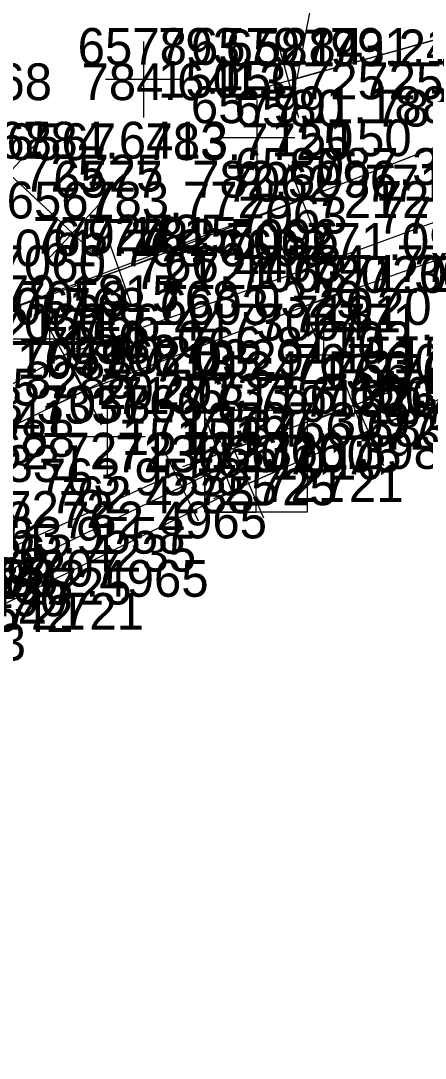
# Model space of a CAD drawing. Extents: x 1602514 to 1609837, y 863887 to 871157.
# Drawn here: x 1604583.5 to 1604666.7, y 865888.8 to 866102.1 of the extents above; entities that cross this region are included whole.
import ezdxf

# ---------------------------------------------------------------- set-up
doc = ezdxf.new("R2010")
doc.units = 0
for name, color, linetype in [('Default', 7, 'Continuous'), ('Survey-Point', 7, 'Continuous'), ('Survey-Spot bituminous', 7, 'Continuous'), ('Survey-Spot dirt', 7, 'Continuous'), ('Survey-Text-Elevation', 7, 'Continuous'), ('Survey-Text-Feature', 7, 'Continuous'), ('Survey-Text-Name and Number', 7, 'Continuous'), ('Survey-Utility-poles', 7, 'Continuous'), ('Survey-Vegetation trees', 7, 'Continuous')]:
    doc.layers.add(name, color=color, linetype=linetype)

msp = doc.modelspace()

# ---------------------------------------------------------------- linework, layer by layer
at = {"layer": 'Default'}
for points in [[(1604317.66, 865825.88), (1604343.15, 865856.06), (1604377.77, 865885.95), (1604413.36, 865926.28), (1604468.55, 865975.61), (1604530.26, 866007.99), (1604571, 866039.19), (1604603.77, 866050.72), (1604641.34, 866065.32), (1604709.14, 866091.96), (1604755.83, 866103.01), (1604799.76, 866108.85), (1604851.09, 866123.18), (1604880.6, 866134.38), (1604938.3, 866169.31)], [(1604317.66, 865825.88), (1604343.15, 865856.06), (1604377.77, 865885.95), (1604413.36, 865926.28), (1604468.55, 865975.61), (1604530.26, 866007.99), (1604571, 866039.19), (1604603.77, 866050.72), (1604641.34, 866065.32), (1604709.14, 866091.96), (1604755.83, 866103.01), (1604799.76, 866108.85), (1604851.09, 866123.18), (1604880.6, 866134.38), (1604938.3, 866169.31)], [(1604418.07, 865911.75), (1604456.72, 865946.46), (1604484.55, 865966.8), (1604519.27, 865986.42), (1604552.11, 866004.25), (1604596.62, 866026.02), (1604641.77, 866043.32), (1604684.55, 866058.32), (1604714.78, 866069.08), (1604743.56, 866078.38), (1604785.26, 866088.44), (1604832.44, 866095.89), (1604871.37, 866104.92), (1604903.81, 866116.87), (1604930.07, 866130.29), (1604954.76, 866146.48)], [(1604418.07, 865911.75), (1604456.72, 865946.46), (1604484.55, 865966.8), (1604519.27, 865986.42), (1604552.11, 866004.25), (1604596.62, 866026.02), (1604641.77, 866043.32), (1604684.55, 866058.32), (1604714.78, 866069.08), (1604743.56, 866078.38), (1604785.26, 866088.44), (1604832.44, 866095.89), (1604871.37, 866104.92), (1604903.81, 866116.87), (1604930.07, 866130.29), (1604954.76, 866146.48)], [(1604969.01, 866130.08), (1604947.53, 866114.66), (1604915.9, 866098.08), (1604878.31, 866083.75), (1604838.9, 866074.21), (1604795.51, 866067.39), (1604763.14, 866059.96), (1604741.7, 866054.99), (1604695.88, 866039.38), (1604651.97, 866023), (1604624.19, 866013.05), (1604572.23, 865989.52), (1604533.06, 865968.94), (1604507.4, 865954.89), (1604477.08, 865934.29), (1604465.98, 865925.57), (1604435.67, 865897.76)], [(1604969.01, 866130.08), (1604947.53, 866114.66), (1604915.9, 866098.08), (1604878.31, 866083.75), (1604838.9, 866074.21), (1604795.51, 866067.39), (1604763.14, 866059.96), (1604741.7, 866054.99), (1604695.88, 866039.38), (1604651.97, 866023), (1604624.19, 866013.05), (1604572.23, 865989.52), (1604533.06, 865968.94), (1604507.4, 865954.89), (1604477.08, 865934.29), (1604465.98, 865925.57), (1604435.67, 865897.76)], [(1604947.43, 866111.35), (1604916.99, 866095.23), (1604887.83, 866078.59), (1604869.51, 866073.57), (1604839.7, 866068.1), (1604796.01, 866064.89), (1604764.05, 866057.49), (1604744.43, 866051.86), (1604696.67, 866036.33), (1604655.01, 866017.68), (1604630.39, 866006.95), (1604577.01, 865980.66), (1604537.2, 865961.45), (1604527.45, 865955.57)], [(1604947.43, 866111.35), (1604916.99, 866095.23), (1604887.83, 866078.59), (1604869.51, 866073.57), (1604839.7, 866068.1), (1604796.01, 866064.89), (1604764.05, 866057.49), (1604744.43, 866051.86), (1604696.67, 866036.33), (1604655.01, 866017.68), (1604630.39, 866006.95), (1604577.01, 865980.66), (1604537.2, 865961.45), (1604527.45, 865955.57)], [(1604638.56, 866089.7), (1604688.07, 866103.57), (1604751.24, 866108.42)], [(1604638.56, 866089.7), (1604688.07, 866103.57), (1604751.24, 866108.42)], [(1604594.18, 866058.42), (1604581.01, 866070.74), (1604536, 866101.64)], [(1604594.18, 866058.42), (1604581.01, 866070.74), (1604536, 866101.64)], [(1604322.98, 865821.98), (1604323.18, 865824.62), (1604347.39, 865848.47), (1604386.06, 865884.59), (1604416.66, 865913.17), (1604455.42, 865948.07), (1604483.63, 865969.92), (1604515.11, 865988.99), (1604549.54, 866009.43), (1604592.4, 866033.32), (1604639.22, 866049.9), (1604682.4, 866065.75), (1604710.78, 866076.01), (1604734.96, 866082.18)], [(1604322.98, 865821.98), (1604323.18, 865824.62), (1604347.39, 865848.47), (1604386.06, 865884.59), (1604416.66, 865913.17), (1604455.42, 865948.07), (1604483.63, 865969.92), (1604515.11, 865988.99), (1604549.54, 866009.43), (1604592.4, 866033.32), (1604639.22, 866049.9), (1604682.4, 866065.75), (1604710.78, 866076.01), (1604734.96, 866082.18)], [(1604616.65, 866006.26), (1604574.45, 865985.84), (1604535.94, 865964.64), (1604524.8, 865957.18), (1604517.47, 865951.2), (1604513.27, 865945.54)], [(1604616.65, 866006.26), (1604574.45, 865985.84), (1604535.94, 865964.64), (1604524.8, 865957.18), (1604517.47, 865951.2), (1604513.27, 865945.54)]]:
    msp.add_lwpolyline(points, dxfattribs=at)
at = {"layer": 'Survey-Point'}
for p, q in [((1604636.45, 866097.23), (1604640.67, 866082.18)), ((1604646.08, 866091.81), (1604631.04, 866087.6)), ((1604575.31, 866076.08), (1604586.72, 866065.4)), ((1604575.68, 866065.04), (1604586.35, 866076.44)), ((1604638.51, 866072.6), (1604644.17, 866058.04)), ((1604648.62, 866068.15), (1604634.06, 866062.49)), ((1604588.47, 866063.76), (1604599.88, 866053.08)), ((1604588.84, 866052.72), (1604599.51, 866064.13)), ((1604601.17, 866058.09), (1604606.36, 866043.35)), ((1604636.61, 866057.26), (1604641.83, 866042.53)), ((1604611.14, 866053.32), (1604596.4, 866048.13)), ((1604646.59, 866052.51), (1604631.86, 866047.29)), ((1604638.98, 866050.61), (1604644.56, 866036.02)), ((1604649.07, 866046.11), (1604634.47, 866040.52)), ((1604588.59, 866040.14), (1604596.2, 866026.5)), ((1604599.22, 866037.12), (1604585.57, 866029.52)), ((1604593.18, 866033.04), (1604600.05, 866019.01)), ((1604603.64, 866029.46), (1604589.6, 866022.59)), ((1604654.7, 866015.68), (1604649.24, 866030.32)), ((1604644.65, 866020.27), (1604659.29, 866025.73)), ((1604658.21, 866010.55), (1604651.82, 866024.81)), ((1604626.83, 866005.69), (1604621.56, 866020.4)), ((1604647.88, 866014.49), (1604662.14, 866020.87)), ((1604616.84, 866010.41), (1604631.55, 866015.68)), ((1604633.5, 865999.79), (1604627.27, 866014.12)), ((1604620.06, 865999.23), (1604613.25, 866013.29)), ((1604623.22, 866003.83), (1604637.55, 866010.07)), ((1604609.62, 866002.86), (1604623.69, 866009.66)), ((1604570, 865977.2), (1604584.02, 865984.11))]:
    msp.add_line(p, q, dxfattribs=at)
at = {"layer": 'Survey-Spot bituminous'}
for p, q in [((1604645.78, 866041.16), (1604645.78, 866025.54)), ((1604653.59, 866033.35), (1604637.97, 866033.35)), ((1604601.29, 866024.37), (1604601.29, 866008.75)), ((1604609.11, 866016.56), (1604593.48, 866016.56))]:
    msp.add_line(p, q, dxfattribs=at)
at = {"layer": 'Survey-Spot dirt'}
for p, q in [((1604608.77, 866097.81), (1604608.77, 866082.19)), ((1604616.58, 866090), (1604600.96, 866090)), ((1604632.06, 866085.81), (1604632.06, 866070.19)), ((1604639.87, 866078), (1604624.25, 866078)), ((1604589.42, 866044.39), (1604589.42, 866028.77)), ((1604597.23, 866036.58), (1604581.61, 866036.58))]:
    msp.add_line(p, q, dxfattribs=at)
at = {"layer": 'Survey-Utility-poles'}
for points in [[(1604621.42, 866001.03), (1604631.92, 866001.03), (1604631.92, 866022.04), (1604621.42, 866022.04)], [(1604621.42, 866022.04), (1604642.43, 866022.04), (1604642.43, 866001.03), (1604621.42, 866001.03)]]:
    msp.add_lwpolyline(points, close=True, dxfattribs=at)
at = {"layer": 'Survey-Vegetation trees'}
for points in [[(1604936.33, 866180.61), (1604828.34, 866126.3), (1604827.66, 866144.66), (1604799.29, 866162.35), (1604737.82, 866156.32), (1604693.89, 866174.66), (1604669.04, 866176.96), (1604670.6, 866142.06), (1604659.79, 866117.8), (1604667.53, 866114.56), (1604679.44, 866101.15), (1604640.36, 866090.2), (1604645.49, 866116.93), (1604602.11, 866123.38), (1604531.29, 866143.38), (1604483.77, 866157.5), (1604441.77, 866144.36), (1604421.63, 866112.25)], [(1604243.16, 865754.91), (1604317.66, 865825.88), (1604343.54, 865856.39), (1604412.96, 865925.83), (1604470.6, 865976.69), (1604532.4, 866009.63), (1604574.44, 866040.4), (1604646.35, 866067.29), (1604709.79, 866092.12), (1604761.9, 866103.82), (1604800.74, 866109.12), (1604857.49, 866106.02), (1604919.6, 866129.97), (1604961.14, 866155.01)]]:
    msp.add_lwpolyline(points, dxfattribs=at)

# ---------------------------------------------------------------- texts
at = {"layer": 'Survey-Text-Elevation'}
for s, p in [('793.5284', (1604611.77, 866093)), ('793.2423', (1604641.56, 866092.7)), ('791.1881', (1604647.06, 866093)), ('784.6413', (1604596.01, 866085.74)), ('791.1881', (1604635.06, 866081)), ('787.3344', (1604656.34, 866080.32)), ('784.6413', (1604584.01, 866073.74)), ('783.7725', (1604609.18, 866073.42)), ('787.3344', (1604644.34, 866068.32)), ('782.5096', (1604618.77, 866065.72)), ('771.0973', (1604654.22, 866064.9)), ('783.7725', (1604597.18, 866061.42)), ('771.3698', (1604656.77, 866058.32)), ('779.1815', (1604586, 866054.19)), ('782.5096', (1604606.77, 866053.72)), ('768.6603', (1604604.42, 866051.58)), ('771.0973', (1604642.22, 866052.9)), ('766.4473', (1604607.4, 866048.32)), ('771.2481', (1604660.78, 866048.35)), ('771.3698', (1604644.77, 866046.32)), ('779.1815', (1604574, 866042.19)), ('768.0329', (1604611.62, 866041.02)), ('768.6603', (1604592.42, 866039.58)), ('766.4473', (1604595.4, 866036.32)), ('771.2481', (1604648.78, 866036.35)), ('766.8170', (1604616.29, 866031.56)), ('764.1641', (1604563.08, 866028.51)), ('768.0329', (1604599.62, 866029.02)), ('767.3097', (1604639.19, 866028.05)), ('766.6830', (1604646.92, 866026.53)), ('770.0671', (1604654.97, 866026)), ('761.8288', (1604564.54, 866024.43)), ('771.6955', (1604545.26, 866022.99)), ('766.1005', (1604631.65, 866021.26)), ('766.3988', (1604645.39, 866021.95)), ('763.3331', (1604567.11, 866019.25)), ('766.8170', (1604604.29, 866019.56)), ('768.6179', (1604658.01, 866020.68)), ('764.1641', (1604551.08, 866016.51)), ('767.3097', (1604627.19, 866016.05)), ('766.6830', (1604634.92, 866014.53)), ('761.8288', (1604552.54, 866012.43)), ('762.7272', (1604572.46, 866009.83)), ('766.1005', (1604619.65, 866009.26)), ('766.3988', (1604633.39, 866009.95)), ('763.3331', (1604555.11, 866007.25)), ('763.9558', (1604587.23, 866004.52)), ('762.4235', (1604589.45, 866000.84)), ('762.7272', (1604560.46, 865997.83)), ('762.4965', (1604592.01, 865995.66)), ('763.9558', (1604575.23, 865992.52)), ('762.4235', (1604577.45, 865988.84)), ('760.0898', (1604548.06, 865983.94)), ('762.4965', (1604580.01, 865983.66)), ('758.7490', (1604550.94, 865979.64)), ('758.4542', (1604552.2, 865976.45)), ('757.4563', (1604542.45, 865970.57))]:
    msp.add_text(s, height=7.56, dxfattribs=at).set_placement(p)
at = {"layer": 'Survey-Text-Feature'}
for s, p in [('150', (1604611.77, 866086.22)), ('150', (1604623.77, 866086.22)), ('725', (1604641.56, 866085.92)), ('725', (1604653.56, 866085.92)), ('150', (1604635.06, 866074.22)), ('150', (1604647.06, 866074.22)), ('725', (1604584.01, 866066.96)), ('725', (1604596.01, 866066.96)), ('721', (1604644.34, 866061.54)), ('721', (1604656.34, 866061.54)), ('725', (1604597.18, 866054.64)), ('725', (1604609.18, 866054.64)), ('721', (1604606.77, 866046.94)), ('721', (1604618.77, 866046.94)), ('720', (1604642.22, 866046.12)), ('720', (1604654.22, 866046.12)), ('207', (1604644.77, 866039.54)), ('207', (1604656.77, 866039.54)), ('721', (1604574, 866035.41)), ('721', (1604586, 866035.41)), ('150', (1604592.42, 866032.8)), ('150', (1604604.42, 866032.8)), ('720', (1604595.4, 866029.54)), ('720', (1604607.4, 866029.54)), ('151', (1604648.78, 866029.57)), ('151', (1604660.78, 866029.57)), ('207', (1604599.62, 866022.24)), ('207', (1604611.62, 866022.24)), ('207', (1604654.97, 866019.22)), ('721', (1604658.01, 866013.9)), ('151', (1604604.29, 866012.78)), ('151', (1604616.29, 866012.78)), ('207', (1604627.19, 866009.27)), ('207', (1604639.19, 866009.27)), ('10', (1604634.92, 866007.75)), ('10', (1604646.92, 866007.75)), ('725', (1604619.65, 866002.48)), ('725', (1604631.65, 866002.48)), ('721', (1604633.39, 866003.17)), ('721', (1604645.39, 866003.17)), ('151', (1604572.46, 865991.05)), ('207', (1604575.23, 865985.74)), ('207', (1604587.23, 865985.74)), ('725', (1604577.45, 865982.06)), ('725', (1604589.45, 865982.06)), ('721', (1604580.01, 865976.88)), ('721', (1604592.01, 865976.88))]:
    msp.add_text(s, height=7.56, dxfattribs=at).set_placement(p)
at = {"layer": 'Survey-Text-Name and Number'}
for s, p in [('6578', (1604595.23, 866093)), ('6579', (1604618.51, 866093)), ('6581', (1604625.68, 866092.7)), ('6568', (1604567.47, 866085.74)), ('6579', (1604618.51, 866081)), ('6580', (1604627.5, 866080.32)), ('6568', (1604567.47, 866073.74)), ('6567', (1604580.63, 866073.42)), ('6580', (1604627.5, 866068.32)), ('6577', (1604590.22, 866065.72)), ('7062', (1604625.68, 866064.9)), ('6567', (1604580.63, 866061.42)), ('7063', (1604628.23, 866058.32)), ('6577', (1604590.22, 866053.72)), ('7061', (1604576.66, 866051.58)), ('7062', (1604625.68, 866052.9)), ('7060', (1604578.56, 866048.32)), ('7064', (1604632.24, 866048.35)), ('7063', (1604628.23, 866046.32)), ('7059', (1604583.07, 866041.02)), ('7061', (1604576.54, 866039.58)), ('7060', (1604578.56, 866036.32)), ('7064', (1604632.24, 866036.35)), ('7131', (1604639.22, 866038)), ('7132', (1604641.47, 866032.68)), ('7058', (1604587.75, 866031.56)), ('7059', (1604583.07, 866029.02)), ('7135', (1604610.64, 866028.05)), ('7134', (1604618.38, 866026.53)), ('7131', (1604639.09, 866026)), ('7136', (1604602.93, 866021.26)), ('7133', (1604616.84, 866021.95)), ('7058', (1604587.75, 866019.56)), ('7132', (1604641.47, 866020.68)), ('7135', (1604610.64, 866016.05)), ('7134', (1604618.38, 866014.53)), ('7136', (1604602.93, 866009.26)), ('7133', (1604616.84, 866009.95)), ('7138', (1604563.46, 865995.66)), ('7138', (1604563.46, 865983.66))]:
    msp.add_text(s, height=7.56, dxfattribs=at).set_placement(p)

doc.saveas('drawing.dxf')
